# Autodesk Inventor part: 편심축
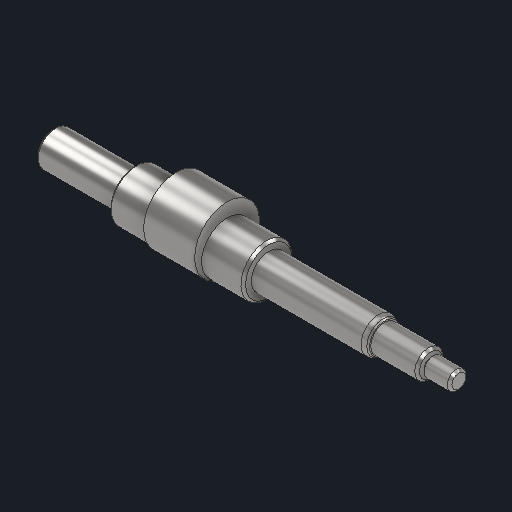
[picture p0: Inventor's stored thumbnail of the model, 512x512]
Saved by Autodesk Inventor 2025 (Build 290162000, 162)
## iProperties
Created: 2025-08
Part Number: 편심축
Material: 강철, 연강
Document SubType Name: Modeling
Designer: infra002
Density: 7.86 g/cm^3
Appearance: 기본값
Author: jhkim
Sending System: Autodesk Inventor 2026
Preprocessor: ST-DEVELOPER v20.1
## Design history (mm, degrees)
feature "솔리드1"
node "솔리드2"
